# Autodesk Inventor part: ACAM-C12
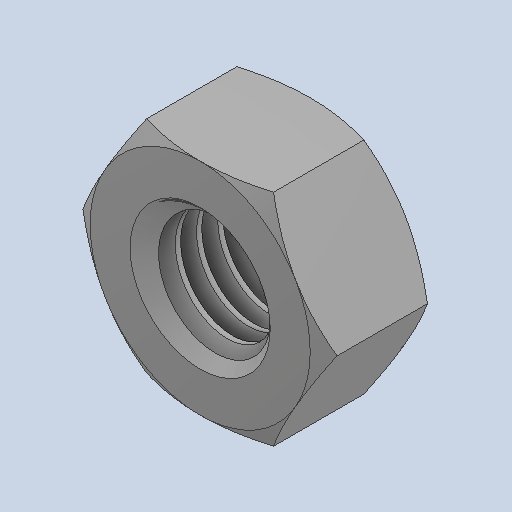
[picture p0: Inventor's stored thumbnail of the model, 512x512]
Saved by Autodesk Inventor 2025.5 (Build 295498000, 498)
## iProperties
Created: 2019-05
Part Number: ACAM-C12
Material: Genérico
Description: Tuerca hexagonal M8
Document SubType Name: Modeling
Designer: Luis M
Density: 1 g/cm^3
Appearance: Valor por defecto
Sending System: SolidWorks 2018
Preprocessor: SwSTEP 2.0
Material_BOM: Por especificar
Proceso_BOM: Comercial
Title: M8 Nut.STEP
Revision Number: HERHANGÝ
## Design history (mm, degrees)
feature "Kes-Süpür1"
node "Sólido1"
